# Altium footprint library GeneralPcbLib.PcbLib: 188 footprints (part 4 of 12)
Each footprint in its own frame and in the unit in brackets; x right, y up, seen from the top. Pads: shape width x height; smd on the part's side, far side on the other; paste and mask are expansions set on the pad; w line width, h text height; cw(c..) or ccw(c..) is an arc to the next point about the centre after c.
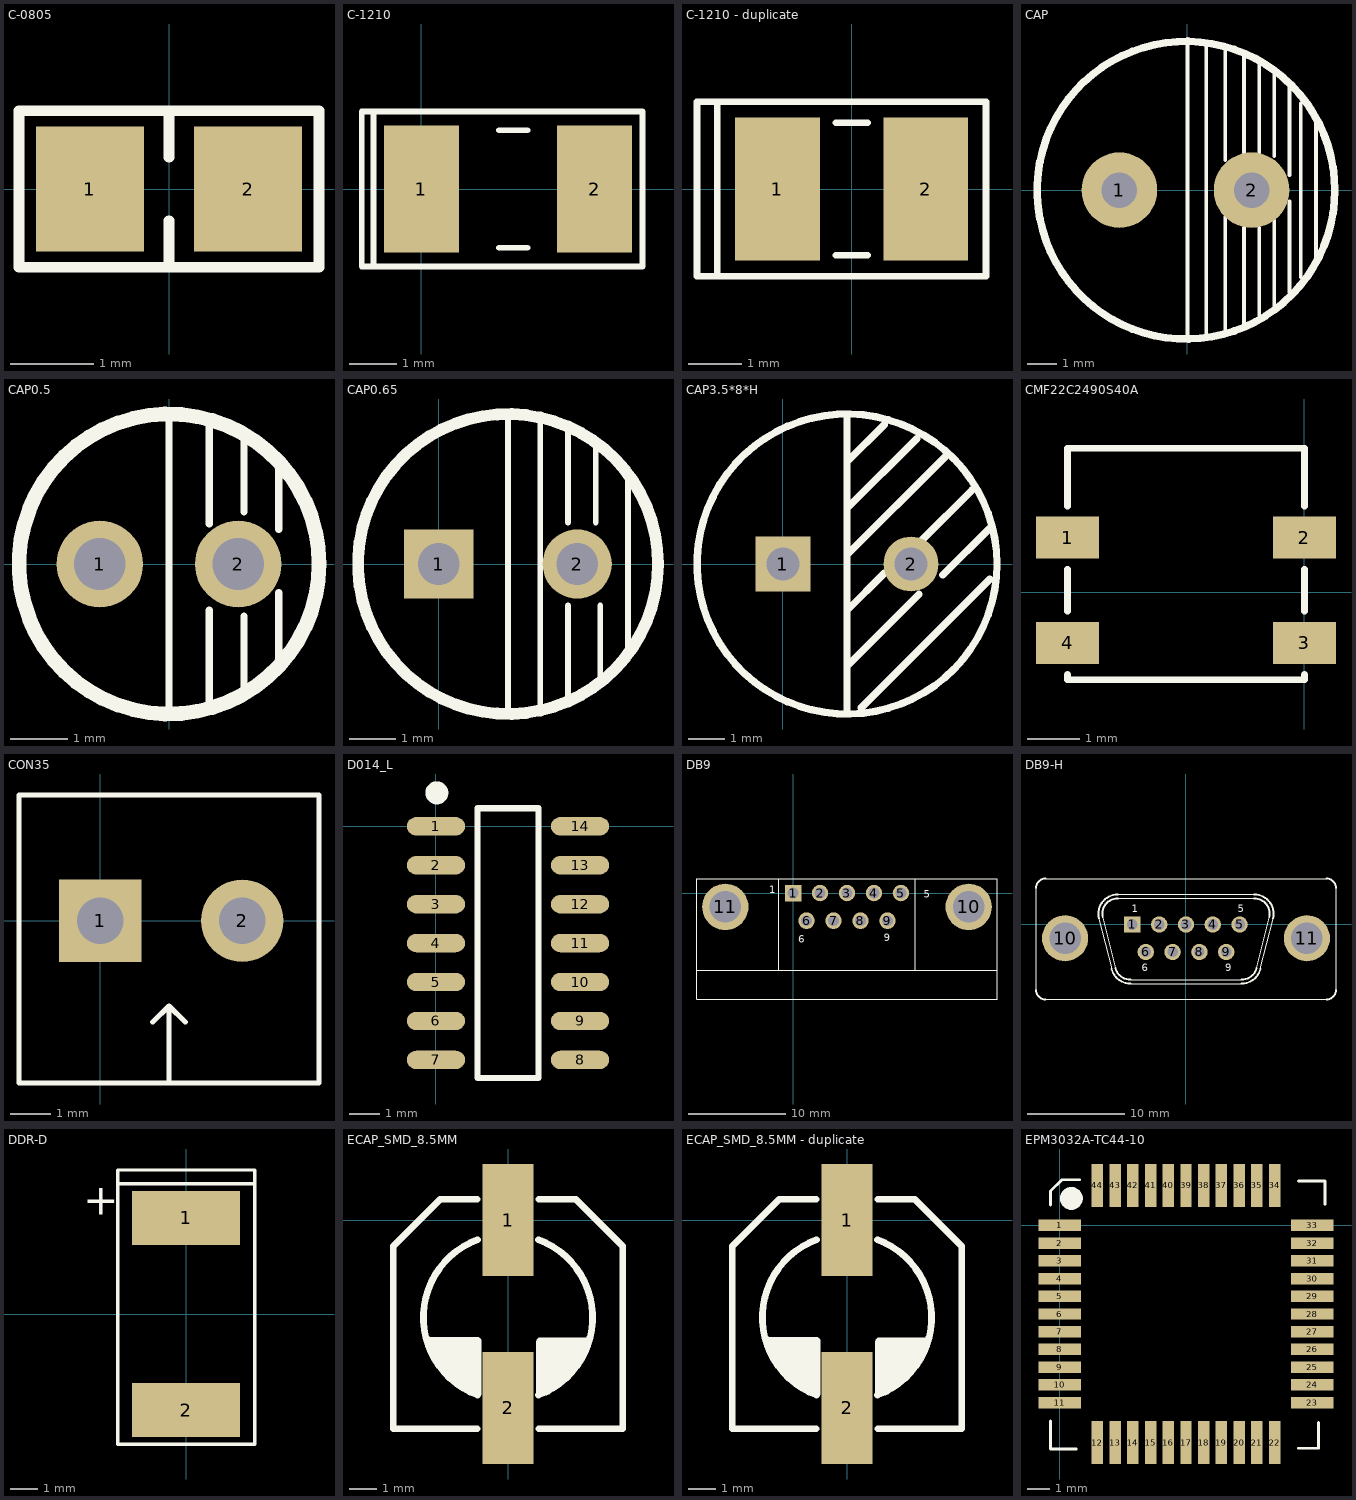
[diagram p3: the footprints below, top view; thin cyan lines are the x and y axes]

## C-0805 [mm]
pads (2):
  rect 1.3x1.5 smd: 1(-0.95,0) 2(0.95,0)
Top Overlay:
  lines w0.127: 0,-0.94 0,-0.381 ; 0,0.381 0,0.889 ; -1.803,-0.94 1.803,-0.94 1.803,0.94 -1.803,0.94 -1.803,-0.94

## C-1210 [mm]
pads (2):
  rect 1.6x2.7 smd: 1(0,0) 2(3.683,0)
Top Overlay:
  lines w0.127: 1.654,-1.25 2.254,-1.25 ; 1.654,1.25 2.254,1.25 ; -1.016,-1.651 -1.016,1.651 ; -1.016,-1.651 4.699,-1.651 4.699,1.651 -1.016,1.651 ; -1.016,-1.651 -1.27,-1.651 -1.27,1.651 -1.016,1.651

## C-1210 - duplicate [mm]
height 4
pads (2):
  rect 1.6x2.7 smd: 1(-1.4,0) 2(1.4,0)
Top Overlay:
  lines w0.127: -0.3,-1.25 0.3,-1.25 ; -0.3,1.25 0.3,1.25 ; -2.54,-1.651 -2.921,-1.651 -2.921,1.651 -2.54,1.651 ; -2.54,-1.651 2.54,-1.651 2.54,1.651 -2.54,1.651 ; -2.54,-1.651 -2.54,1.651

## CAP [mm] "180uF,330uF"
pads (2):
  round 2.54 hole 1.2: 1(-2.286,0) 2(2.159,0)
Top Overlay:
  circle w0.254: c-0.047,0 r5
  lines w0.127: -0.127,4.953 0,5.08 0,0 0,-4.953 ; 0.635,-4.953 0.635,4.826 ; 1.27,-4.826 1.27,-0.889 ; 1.27,1.016 1.27,4.699 ; 1.905,-4.572 1.905,-1.27 ; 1.905,1.27 1.905,4.572 ; 2.413,-4.191 2.413,-1.27 ; 2.413,1.27 2.413,4.318 ; 2.921,-3.937 2.921,-1.016 ; 2.921,1.143 2.921,3.937 ; 3.429,-3.429 3.429,-0.381 ; 3.429,0.508 3.429,3.556 ; 3.81,-2.921 3.81,2.921 ; 4.318,-2.286 4.318,2.286

## CAP0.5 [mm] "47uF"
pads (2):
  round 1.5 hole 0.9: 1(-1.2,0) 2(1.2,0)
Top Overlay:
  circle w0.254: c0,0 r2.6
  lines w0.127: 0,-2.6 0,2.6 ; 0.7,-2.5 0.7,-0.8 ; 0.7,0.7 0.7,2.5 ; 1.3,-2.3 1.3,-0.9 ; 1.3,0.9 1.3,2.2 ; 1.9,-1.7 1.9,-0.5 ; 1.9,0.6 1.9,1.7
3D body: height 13.03, standoff -3.01, extent -3.181,-3.099 3.17,3.252

## CAP0.65 [mm] "100uF"
height 10.16
pads (2):
  rect 1.5x1.5 hole 0.9: 1(0,0)
  round 1.5 hole 0.9: 2(3,0)
Top Overlay:
  circle w0.254: c1.5,0 r3.25
  lines w0.127: 1.5,-3.2 1.5,3.2 ; 2.2,-3.1 2.2,3.1 ; 2.8,-2.9 2.8,-0.9 ; 2.8,0.9 2.8,2.9 ; 3.4,0.9 3.4,2.5 ; 3.5,-2.5 3.5,-0.9 ; 4.1,-1.8 4.1,1.9

## CAP3.5*8*H [mm] "330uF/25V"
height 15
pads (2):
  rect 1.5x1.5 hole 0.9: 1(0,0)
  round 1.5 hole 0.9: 2(3.5,0)
Top Overlay:
  circle w0.2: c1.75,0 r4.1
  lines w0.203: 1.75,-4.064 1.75,4.039 ; 1.75,-2.794 3.719,-0.826 ; 1.75,-1.27 2.766,-0.254 ; 1.75,0.127 1.75,0.254 4.417,2.921 ; 2.142,-3.926 5.653,-0.415 ; 2.766,3.81 1.75,2.794 1.75,1.524 3.655,3.429 ; 3.782,0.635 5.179,2.032 ; 4.37,-0.301 5.64,0.969

## CMF22C2490S40A [mm]
pads (4):
  rect 1.2x0.8 smd: 1(-4.5,1.035) 2(0,1.035) 3(0,-0.965) 4(-4.5,-0.965)
Top Overlay:
  lines w0.127: -4.5,-1.565 -4.5,-1.665 0,-1.665 0,-1.565 ; -4.5,-0.365 -4.5,0.435 ; -4.5,1.635 -4.5,2.735 -0.1,2.735 0,2.735 0,1.635 ; 0,-0.365 0,0.435

## CON35 [mil] "3.5MM接线端子"
pads (2):
  rect 80x80 hole 45: 1(0,0)
  round 80 hole 45: 2(138,0)
Top Overlay:
  lines w5: 51.18,-98.43 66.93,-82.68 ; 66.93,-157.48 66.93,-82.68 ; 82.68,-98.43 66.93,-82.68 ; -78.74,-157.48 212.6,-157.48 212.6,122.05 -78.74,122.05 -78.74,-157.48

## D014_L [mm]
pads (14):
  oval 1.9x0.6 smd: 1(0,0) 2(0,-1.27) 3(0,-2.54) 4(0,-3.81) 5(0,-5.08) 6(0,-6.35) 7(0,-7.62) 8(4.7,-7.62) 9(4.7,-6.35) 10(4.7,-5.08) 11(4.7,-3.81) 12(4.7,-2.54) 13(4.7,-1.27) 14(4.7,0)
Top Overlay:
  circle w0.5: c0.027,1.092 r0.125
  lines w0.2: 1.35,-8.21 1.35,0.59 3.35,0.59 3.35,-8.21 1.35,-8.21
3D body: height 1.75, standoff 0, extent 0.4,-8.135 4.3,0.515

## DB9 [mm]
pads (11):
  rect 1.69x1.69 hole 1.09: 1(0,0)
  round 1.69 hole 1.09: 2(2.77,0) 3(5.54,0) 4(8.31,0) 5(11.08,0) 6(1.385,-2.84) 7(4.155,-2.84) 8(6.925,-2.84) 9(9.695,-2.84)
  round 4.76 hole 3.26: 10(18.035,-1.42) 11(-6.955,-1.42)
Top Overlay:
  lines w0.127: -9.86,-7.92 20.94,-7.92 ; -1.46,-7.92 -1.46,1.48 ; 12.54,-7.92 12.54,1.48 ; -9.86,-10.92 -9.86,1.48 20.94,1.48 20.94,-10.92 -9.86,-10.92
  text "1" at -2.461,0.002 h0.76
  text "5" at 13.414,-0.506 h0.76
  text "9" at 1.222,-4.316 h0.76
  text "6" at 9.985,-4.189 h0.76

## DB9-H [mm] "立式DB9公头"
pads (11):
  rect 1.69x1.69 hole 1.09: 1(-5.54,0)
  round 1.69 hole 1.09: 2(-2.77,0) 3(0,0) 4(2.77,0) 5(5.54,0) 6(-4.155,-2.84) 7(-1.385,-2.84) 8(1.385,-2.84) 9(4.155,-2.84)
  round 4.76 hole 3.26: 10(-12.495,-1.42) 11(12.495,-1.42)
Top Overlay:
  lines w0.127: -15.5,-6.75 -15.5,3.75 ; -14.5,-7.75 14.5,-7.75 ; -14.5,4.75 14.5,4.75 ; -8.991,0.616 -7.694,-4.584 ; -8.602,0.713 -7.306,-4.487 ; -7.05,2.7 7.05,2.7 ; -7.05,3.1 7.05,3.1 ; -5.753,-6.1 5.753,-6.1 ; -5.753,-5.7 5.753,-5.7 ; 7.306,-4.487 8.602,0.713 ; 7.694,-4.584 8.991,0.616 ; 15.5,-6.75 15.5,3.75
  lines w0.203: -15.5,-6.75 ccw(c-14.5,-6.75) -14.5,-7.75 ; -15.5,3.75 cw(c-14.5,3.75) -14.5,4.75 ; -8.991,0.616 cw(c-7.05,1.1) -7.05,3.1 ; -8.602,0.713 cw(c-7.05,1.1) -7.05,2.7 ; -7.694,-4.584 ccw(c-5.753,-4.1) -5.753,-6.1 ; -7.306,-4.487 ccw(c-5.753,-4.1) -5.753,-5.7 ; 5.753,-6.1 ccw(c5.753,-4.1) 7.694,-4.584 ; 5.753,-5.7 ccw(c5.753,-4.1) 7.306,-4.487 ; 7.05,2.7 cw(c7.05,1.1) 8.602,0.713 ; 7.05,3.1 cw(c7.05,1.1) 8.991,0.616 ; 14.5,-7.75 ccw(c14.5,-6.75) 15.5,-6.75 ; 14.5,4.75 cw(c14.5,3.75) 15.5,3.75
  text "6" at -4.572,-4.826 h0.76
  text "9" at 4.064,-4.826 h0.76
  text "5" at 5.334,1.27 h0.76
  text "1" at -5.588,1.27 h0.76

## DDR-D [mm] "胆电容-大的"
pads (2):
  rect 4x2 smd: 1(0,3.556) 2(0,-3.556)
Top Overlay:
  lines w0.127: -2.54,4.826 2.54,4.826 ; -2.54,-4.826 -2.54,5.334 2.54,5.334 2.54,-4.826 -2.54,-4.826
  text "+" at -3.81,3.683 h1.14

## ECAP_SMD_8.5MM [mm] "铝电解电容"
height 13
pads (2):
  rect 1.9x4.15 smd: 1(0,0) 2(0,-6.95)
Top Overlay:
  lines w0.25: -2.877,-4.725 -1.127,-4.725 ; -2.627,-5.225 -1.127,-5.225 ; -2.127,-5.725 -1.127,-5.725 ; -1.143,-7.725 -4.25,-7.725 -4.25,-0.975 -2.5,0.775 -1.143,0.775 ; -1.127,-6.475 cw(c-0.064,-3.6) -1.127,-0.725 ; 1.127,-6.475 ccw(c0.064,-3.6) 1.127,-0.725 ; 1.143,-7.725 4.25,-7.725 4.25,-0.975 2.5,0.775 1.143,0.775 ; 1.177,-4.475 2.927,-4.475
  lines w0.3: -2.877,-4.475 -1.127,-4.475 -1.127,-6.425 ; -2.627,-4.975 -1.127,-4.975 ; -2.377,-5.475 -1.127,-5.475 ; -1.627,-5.975 -1.127,-5.975 ; -1.377,-6.225 -1.127,-6.225 ; 1.177,-6.375 1.177,-4.525
  lines w0.4: -2.727,-4.825 -1.377,-6.175 ; 1.427,-6.275 1.427,-4.575 ; 1.727,-6.075 1.727,-4.575 ; 2.027,-5.775 2.027,-4.625 ; 2.277,-5.475 2.277,-4.575 ; 2.527,-5.175 2.527,-4.575 ; 2.677,-4.825 2.677,-4.575

## ECAP_SMD_8.5MM - duplicate [mm] "铝电解电容"
height 13
pads (2):
  rect 1.9x4.15 smd: 1(0,0) 2(0,-6.95)
Top Overlay:
  lines w0.25: -2.877,-4.725 -1.127,-4.725 ; -2.627,-5.225 -1.127,-5.225 ; -2.127,-5.725 -1.127,-5.725 ; -1.143,-7.725 -4.25,-7.725 -4.25,-0.975 -2.5,0.775 -1.143,0.775 ; -1.127,-6.475 cw(c-0.064,-3.6) -1.127,-0.725 ; 1.127,-6.475 ccw(c0.064,-3.6) 1.127,-0.725 ; 1.143,-7.725 4.25,-7.725 4.25,-0.975 2.5,0.775 1.143,0.775 ; 1.177,-4.475 2.927,-4.475
  lines w0.3: -2.877,-4.475 -1.127,-4.475 -1.127,-6.425 ; -2.627,-4.975 -1.127,-4.975 ; -2.377,-5.475 -1.127,-5.475 ; -1.627,-5.975 -1.127,-5.975 ; -1.377,-6.225 -1.127,-6.225 ; 1.177,-6.375 1.177,-4.525
  lines w0.4: -2.727,-4.825 -1.377,-6.175 ; 1.427,-6.275 1.427,-4.575 ; 1.727,-6.075 1.727,-4.575 ; 2.027,-5.775 2.027,-4.625 ; 2.277,-5.475 2.277,-4.575 ; 2.527,-5.175 2.527,-4.575 ; 2.677,-4.825 2.677,-4.575

## EPM3032A-TC44-10 [mil] "FPGA"
pads (44):
  rect 75x20 smd: 1(0,0) 2(0,-31) 3(0,-62) 4(0,-93) 5(0,-124) 6(0,-155) 7(0,-186) 8(0,-217) 9(0,-248) 10(0,-279) 11(0,-310) 23(442,-310) 24(442,-279) 25(442,-248) 26(442,-217) 27(442,-186) 28(442,-155) 29(442,-124) 30(442,-93) 31(442,-62) 32(442,-31) 33(442,0)
  rect 20x75 smd: 12(66,-380) 13(97,-380) 14(128,-380) 15(159,-380) 16(190,-380) 17(221,-380) 18(252,-380) 19(283,-380) 20(314,-380) 21(345,-380) 22(376,-380) 34(376,70) 35(345,70) 36(314,70) 37(283,70) 38(252,70) 39(221,70) 40(190,70) 41(159,70) 42(128,70) 43(97,70) 44(66,70)
Top Overlay:
  circle w20: c20.43,47.24 r10
  lines w5: -16,-342 -16,-391 29,-391 ; -16,36 -16,60 4,80 35,80 ; 418,-390 453,-390 453,-345 ; 418,78 464,78 464,37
